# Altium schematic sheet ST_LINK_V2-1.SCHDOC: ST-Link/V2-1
size A4; Author: Ph.A; SheetNumber: 6; SheetTotal: 6
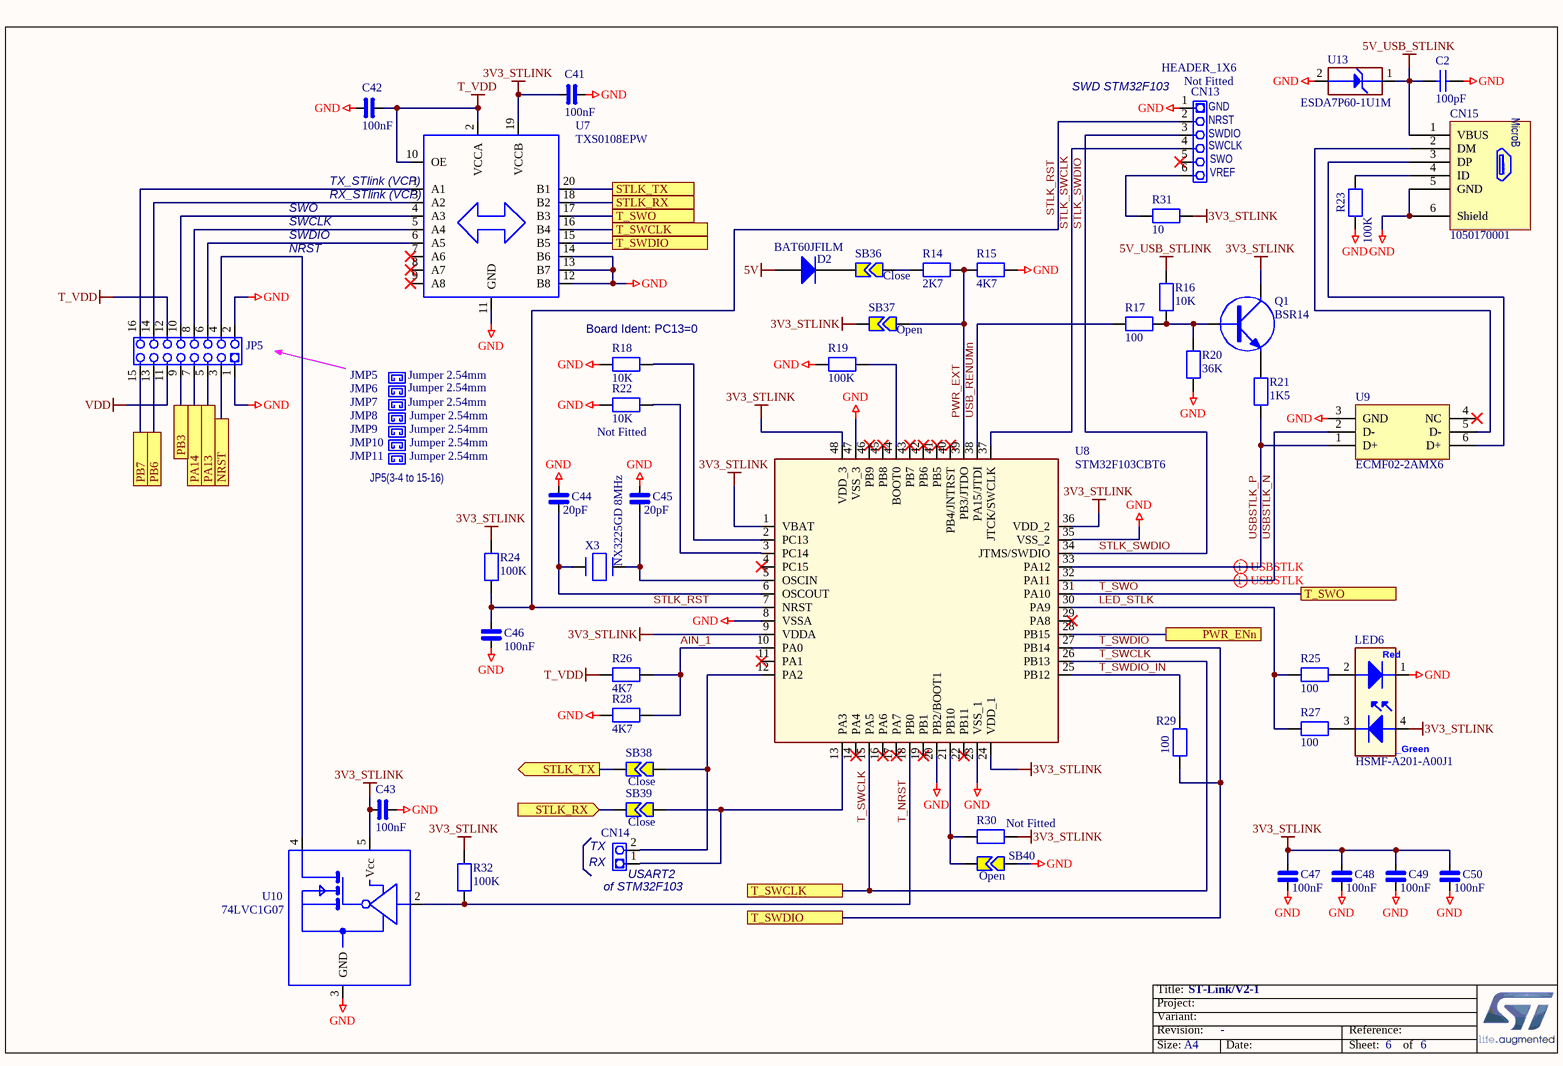
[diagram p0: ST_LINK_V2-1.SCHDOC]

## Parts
C2  value 100pF  [C0402]  (hidden comment: Capacitor)
C41  100nF  [0402_CAP_NPOL]
C42  100nF  [0402_CAP_NPOL]
C43  100nF  [0402_CAP_NPOL]
C44  20pF  [0402_CAP_NPOL]
C45  20pF  [0402_CAP_NPOL]
C46  100nF  [0402_CAP_NPOL]
C47  100nF  [0402_CAP_NPOL]
C48  100nF  [0402_CAP_NPOL]
C49  100nF  [0402_CAP_NPOL]
C50  100nF  [0402_CAP_NPOL]
CN13  HEADER_1X6  Fitted: Not Fitted  [Header NF 1x6x2.54 TH]
CN14  HEADER_1X2  [Header NF 1x2x2.54 TH]  (value not drawn)
CN15  1050170001  [USBMICROB_MOLEX_105017-0001_H2P90]
D2  BAT60JFILM  [SOD-323]
JMP5  Jumper 2.54mm  [Jumper 2.54mm BLACK]
JMP6  Jumper 2.54mm  [Jumper 2.54mm BLACK]
JMP7  Jumper 2.54mm  [Jumper 2.54mm BLACK]
JMP8  Jumper 2.54mm  [Jumper 2.54mm BLACK]
JMP9  Jumper 2.54mm  [Jumper 2.54mm BLACK]
JMP10  Jumper 2.54mm  [Jumper 2.54mm BLACK]
JMP11  Jumper 2.54mm  [Jumper 2.54mm BLACK]
JP5  HEADER_2X8  [Header M 2x8x2.54 TH V]  (value not drawn)
LED6  HSMF-A201-A00J1  [HSMF-A201]
Q1  BSR14  [SOT23-3]
R14  2K7  [0402_RES]
R15  4K7  [0402_RES]
R16  10K  [0402_RES]
R17  100  [0402_RES]
R18  10K  [0402_RES]
R19  100K  [0402_RES]
R20  36K  [0402_RES]
R21  1K5  [0402_RES]
R22  10K  Fitted: Not Fitted  [0402_RES]
R23  100K  [0402_RES]
R24  100K  [0402_RES]
R25  100  [0402_RES]
R26  4K7  [0402_RES]
R27  100  [0402_RES]
R28  4K7  [0402_RES]
R29  100  [0402_RES]
R30  Fitted: Not Fitted  [0402_RES]
R31  10  [0402_RES]
R32  100K  [0402_RES]
SB36  Close  [SB-tiny]
SB37  Open  [SB-tiny]
SB38  Close  [SB-tiny]
SB39  Close  [SB-tiny]
SB40  Open  [SB-tiny]
U7  TXS0108EPW  [TSSOP20]
U8  STM32F103CBT6  [LQFP48_7X7_P050]
U9  ECMF02-2AMX6  [ESD_QFN-6L_1P7X1P5_P050]
U10  74LVC1G07  [SOT353-1]
U13  value ESDA7P60-1U1M  [ESD_QFN2_1P6X1_P125]  (hidden comment: ESD-TRANSIL)
X3  value NX3225GD 8MHz  [CRY_NX3225GD_2P]  (hidden comment: XTAL_2_PINS)

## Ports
NRST, PA13, PA14, PB3, PB6, PB7, PWR_ENn, STLK_RX, STLK_RX (in), STLK_TX, STLK_TX (out), T_SWCLK, T_SWDIO, T_SWO

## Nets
3V3_STLINK: C41.1 C43.1 C47.1 C48.1 C49.1 C50.1 LED6.4 Q1.3(C) R24.2 R30.1 R31.2 R32.2 SB37.1 U7.19(VCCB) U8.1(VBAT) U8.9(VDDA) U8.24(VDD_1) U8.36(VDD_2) U8.48(VDD_3) U10.5(Vcc)
5V: D2.1(A)
5V_USB_STLINK: C2.1 CN15.1(VBUS) R16.2 U13.1(IO1)
GND: C2.2 C41.2 C42.1 C43.2 C44.1 C45.1 C46.1 C47.2 C48.2 C49.2 C50.2 CN13.1 CN15.5(GND) CN15.6(Shield) JP5.1 JP5.2 LED6.1 R15.2 R18.2 R19.1 R20.1 R22.2 R23.1 R28.2 SB40.2 U7.11(GND) U7.12(B8) U7.13(B7) U7.14(B6) U8.8(VSSA) U8.20(PB2/BOOT1) U8.23(VSS_1) U8.35(VSS_2) U8.47(VSS_3) U9.3(GND) U10.3(GND) U13.2(GND)
T_VDD: C42.2 JP5.12 R26.2 U7.2(VCCA) U7.10(OE)
VDD: JP5.11
AIN_1: R26.1 R28.1 U8.10(PA0)
LED_STLK: R25.2 R27.2 U8.30(PA9)
NRST: JP5.3 ; port NRST
PA13: JP5.5 ; port PA13
PA14: JP5.7 ; port PA14
PB3: JP5.9 ; port PB3
PB6: JP5.13 ; port PB6
PB7: JP5.15 ; port PB7
PWR_ENn: U8.28(PB15) ; port PWR_ENn
PWR_EXT: R14.2 R15.1 SB37.2 U8.39(PB3/JTDO)
STLK_RST: C46.2 CN13.2 R24.1 U8.7(NRST)
STLK_RX: SB39.1 U7.18(B2) ; port STLK_RX
STLK_SWCLK: CN13.4 U8.37(JTCK/SWCLK)
STLK_SWDIO: CN13.3 U8.34(JTMS/SWDIO)
STLK_TX: SB38.1 U7.20(B1) ; port STLK_TX
T_NRST: R32.1 U8.18(PB0) U10.2(A)
T_SWCLK: U7.16(B4) U8.15(PA5) U8.26(PB13) ; port T_SWCLK
T_SWDIO: R29.1 U7.15(B5) U8.27(PB14) ; port T_SWDIO
T_SWDIO_IN: R29.2 U8.25(PB12)
T_SWO: U7.17(B3) U8.31(PA10) ; port T_SWO
USB_RENUMn: R17.2 U8.38(PA15/JTDI)
USBSTLK_N: U8.32(PA11) U9.2(D-)
USBSTLK_P: R21.1 U8.33(PA12) U9.1(D+)
NetC44_2: C44.2 U8.6(OSCOUT) X3.2(X2)
NetC45_2: C45.2 U8.5(OSCIN) X3.1(X1)
NetCN13_6: CN13.6 R31.1
NetCN14_1: CN14.1 SB39.2 U8.13(PA3)
NetCN14_2: CN14.2 SB38.2 U8.12(PA2)
NetCN15_2: CN15.2(DM) U9.5(D-)
NetCN15_3: CN15.3(DP) U9.6(D+)
NetCN15_4: CN15.4(ID) R23.2
NetD2_2: D2.2(K) SB36.1
NetJP5_4: JP5.4 U10.4(Y)
NetJP5_6: JP5.6 U7.6(A5)
NetJP5_8: JP5.8 U7.5(A4)
NetJP5_10: JP5.10 U7.4(A3)
NetJP5_14: JP5.14 U7.3(A2)
NetJP5_16: JP5.16 U7.1(A1)
NetLED6_2: LED6.2 R25.1
NetLED6_3: LED6.3 R27.1
NetQ1_1: Q1.1(B) R16.1 R17.1 R20.2
NetQ1_2: Q1.2(E) R21.2
NetR14_1: R14.1 SB36.2
NetR18_1: R18.1 U8.2(PC13)
NetR19_2: R19.2 U8.44(BOOT0)
NetR22_1: R22.1 U8.3(PC14)
NetR30_2: R30.2 SB40.1 U8.21(PB10)

Not connected (* = marked no-connect by the designer): CN13 5*; U7 7(A6)* 8(A7)* 9(A8)*; U8 4(PC15)* 11(PA1)* 14(PA4)* 16(PA6)* 17(PA7)* 19(PB1)* 22(PB11)* 29(PA8)* 40(PB4/JNTRST)* 41(PB5)* 42(PB6)* 43(PB7)* 45(PB8)* 46(PB9)*; U9 4(NC)*

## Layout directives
differential pair; net class DIFF90: USBSTLK_N, USBSTLK_P

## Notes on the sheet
- (near CN13) SWD STM32F103
- (near CN13) SWDIO
- (near CN13) NRST
- (near CN13) GND
- TX_STlink (VCP)
- RX_STlink (VCP)
- (near CN13) SWCLK
- (near CN13) SWO
- (near CN13) VREF
- SWO
- SWCLK
- SWDIO
- NRST
- Board Ident: PC13=0
- (near JMP11) JP5(3-4 to 15-16)
- (near CN14) RX
- TX
- (near CN14) USART2
- (near CN14) of STM32F103

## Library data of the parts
C2 = MCD-00205: Capacitor, MLCC, 100pF, 50V, NPO, 5%, 0402, T=0,5mm; Manufacturer_Part_Number: CC0402JRNPO9BN101; Manufacturer: YAGEO; ECCN_US: EAR99; ECCN_EU: NEC; Provided_By: SUBCO
C41-C50 = CAP_NPOL: Capacitor_not polarized
CN15 = 1050170001: USB-MICRO-B, 1050170001, SMT, MOLEX; Fitted: YES; Ordered_By: Subcon
D2 = Diode: Default Diode; Code - JEDEC: DO-214-AB; Ordered by: STM; ECCN_US/EU: EAR99/NEC
LED6 = LD_BICOLOR_CMS: Bicolor Led; Manuf_1: Avago Technologies; Manuf_2: kingbright; Manuf_Part_2: KAA-3528SURKCGKC
Q1 = 2N2222: 2N2222_SOT23
R14-R32 = RES: Resistor
SB36-SB40 = Strap2: Solder Jumper; Solder: YES
U7 = TXS0108EPW: TXS0108E Bi-directional Level Shifter TSSOP20
U8 = STM32F103CBT6: Medium-density performance line ARM-based 32-bit MCU with 128KB Flash; Manuf_1: STM; ECCN_US/EU: 3A991A2/NEC; Fitted: YES
U9 = MCD-00649: Common mode filter with ESD protection for USB 2.0 interface; Part_Type: Diode; Manufacturer: STMICROELECTRONICS; BMS_Part_Number: 9151138; ECCN_US: EAR99; ECCN_EU: NEC; Provided_By: SUBCO with ST control
U13 = MCD-00251: High power transient voltage suppressor, 7V breakdown; Part_Type: Diode; Manufacturer: STMICROELECTRONICS; BMS_Part_Number: 9179042; ECCN_US: EAR99; ECCN_EU: NEC; Provided_By: SUBCO with ST control
X3 = MCD-00092: Crystal 8MHz, 8pF, +-20ppm, 500ohms max,  SMD; Part_Type: Crystal_Osc; Manufacturer_Part_Number: NX3225GD 8MHz EXS00A-CG04874; Manufacturer: NDK; BMS_Part_Number: 9157029; ECCN_US: EAR99; ECCN_EU: NEC; Provided_By: SUBCO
